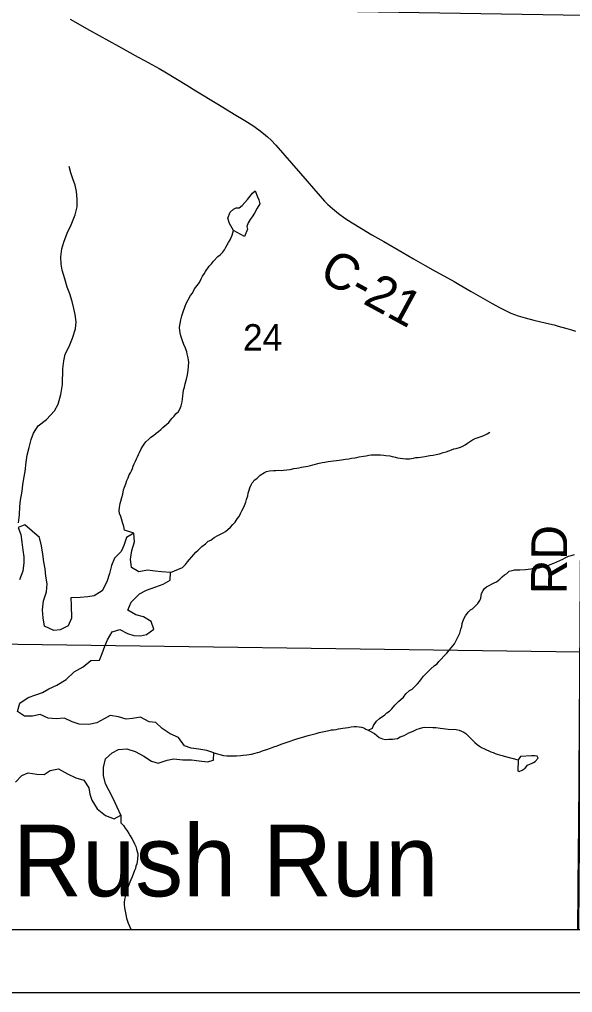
# Model space of a CAD drawing. Extents: x -8.8 to 41.4, y 0 to 34.6.
# Drawn here: x -6.331 to -5.453, y 14 to 15.544 of the extents above; entities that cross this region are included whole.
import ezdxf

# ---------------------------------------------------------------- set-up
doc = ezdxf.new("R2010")
doc.units = 0
for name, color, linetype in [('GM_X_Corporation', 7, 'Continuous'), ('GM_X_County_Road', 7, 'Continuous'), ('GM_X_Minor_River', 7, 'Continuous'), ('GM_X_State_Shield', 7, 'Continuous'), ('GM_X_Township_Road_Text', 7, 'Continuous'), ('GM_X_Township_Text', 7, 'Continuous'), ('GM_X_Unincorporated_Text', 7, 'Continuous'), ('SH_Border', 7, 'Continuous')]:
    doc.layers.add(name, color=color, linetype=linetype)

msp = doc.modelspace()

# ---------------------------------------------------------------- linework, layer by layer
at = {"layer": 'GM_X_Corporation'}
msp.add_lwpolyline([(-8.6743, 18.6925), (-8.6743, 14.1), (-5.4442, 14.1), (-5.4432, 14.2265), (-5.4429, 14.2618), (-5.4404, 14.5882), (-5.4368, 15.0446), (-5.435, 15.3164), (-5.4282, 16.3507), (-5.4212, 16.5483), (-5.4129, 17.3836), (-5.4008, 18.6369)], dxfattribs=at)
for points in [[(-6.4479, 15.5667), (-5.4349, 15.5503), (-5.4351, 15.4586), (-5.4406, 14.5401), (-6.4506, 14.5538)], [(-6.4536, 14.1), (-5.4429, 14.1), (-5.4401, 14.4488), (-5.4406, 14.5401), (-6.4506, 14.5538)]]:
    msp.add_lwpolyline(points, close=True, dxfattribs=at)
at = {"layer": 'GM_X_County_Road'}
msp.add_lwpolyline([(-6.2505, 15.5442), (-6.2195, 15.527), (-6.1739, 15.5016), (-6.1424, 15.4841), (-6.1321, 15.4785), (-6.1092, 15.4658), (-6.0973, 15.4591), (-6.065, 15.4393), (-6.0507, 15.4306), (-6.0151, 15.4089), (-5.9902, 15.3937), (-5.9732, 15.3833), (-5.9606, 15.3753), (-5.9509, 15.3686), (-5.9434, 15.363), (-5.9371, 15.3577), (-5.9313, 15.3521), (-5.924, 15.3444), (-5.9097, 15.328), (-5.8991, 15.3158), (-5.8849, 15.2994), (-5.8743, 15.2872), (-5.8642, 15.2754), (-5.8536, 15.2633), (-5.8464, 15.2556), (-5.8411, 15.2504), (-5.8338, 15.2438), (-5.8242, 15.236), (-5.8141, 15.2287), (-5.8028, 15.2212), (-5.788, 15.2121), (-5.7714, 15.2023), (-5.7618, 15.1967), (-5.7526, 15.1914), (-5.7235, 15.1747), (-5.7052, 15.1641), (-5.687, 15.1535), (-5.6745, 15.1465), (-5.6408, 15.1278), (-5.6327, 15.1232), (-5.6139, 15.1124), (-5.6026, 15.1059), (-5.5805, 15.0932), (-5.5679, 15.0864), (-5.5591, 15.0819), (-5.5507, 15.078), (-5.5391, 15.0737), (-5.5279, 15.0702), (-5.5141, 15.0666), (-5.4942, 15.0619), (-5.4821, 15.059), (-5.4754, 15.0574), (-5.4616, 15.0537), (-5.4544, 15.0515), (-5.4483, 15.0493)], dxfattribs=at)
at = {"layer": 'GM_X_Minor_River'}
for points in [[(-6.3324, 14.7451), (-6.3309, 14.7576), (-6.3301, 14.7709), (-6.3291, 14.7811), (-6.3267, 14.7955), (-6.3253, 14.8053), (-6.3239, 14.8155), (-6.322, 14.8268), (-6.32, 14.8412), (-6.3186, 14.8526), (-6.3155, 14.8646), (-6.3125, 14.8771), (-6.3088, 14.8872), (-6.3012, 14.8988), (-6.288, 14.909), (-6.2751, 14.923), (-6.2695, 14.9335), (-6.2652, 14.9489), (-6.2628, 14.9648), (-6.2621, 14.9895), (-6.2606, 15.0024), (-6.2584, 15.0125), (-6.2519, 15.0249), (-6.2466, 15.038), (-6.242, 15.0527), (-6.2409, 15.0641), (-6.2425, 15.0755), (-6.2444, 15.085), (-6.2471, 15.0961), (-6.251, 15.1084), (-6.2552, 15.1192), (-6.2586, 15.1322), (-6.2631, 15.146), (-6.2647, 15.1555), (-6.2651, 15.1669), (-6.2636, 15.1798), (-6.2606, 15.1903), (-6.2549, 15.2046), (-6.2488, 15.2181), (-6.2426, 15.2339), (-6.2392, 15.2467), (-6.2392, 15.2588), (-6.2404, 15.271), (-6.2424, 15.2806), (-6.2463, 15.2909), (-6.2494, 15.3005), (-6.2521, 15.3105)], [(-5.991, 15.2089), (-5.9976, 15.2201), (-6, 15.2285), (-5.9966, 15.2379), (-5.9908, 15.2427), (-5.9866, 15.2448), (-5.982, 15.2451), (-5.9773, 15.2487), (-5.9687, 15.2583), (-5.9608, 15.2684), (-5.9565, 15.2716), (-5.953, 15.2624), (-5.9509, 15.2574), (-5.9492, 15.2513), (-5.9536, 15.2442), (-5.9576, 15.2364), (-5.9616, 15.2304), (-5.9644, 15.2263), (-5.9679, 15.2211), (-5.97, 15.2155), (-5.969, 15.2109), (-5.9735, 15.1992)], [(-6.0938, 14.9044), (-6.091, 14.9078), (-6.0883, 14.9111), (-6.0851, 14.9145), (-6.0824, 14.9178), (-6.0785, 14.9219), (-6.0761, 14.9256), (-6.074, 14.9305), (-6.0723, 14.9373), (-6.0722, 14.9415), (-6.0717, 14.9464), (-6.0708, 14.9509), (-6.0703, 14.9555), (-6.069, 14.9604), (-6.0677, 14.9657), (-6.0665, 14.9694), (-6.0656, 14.9732), (-6.0639, 14.98), (-6.0634, 14.9834), (-6.0629, 14.9876), (-6.0624, 14.9932), (-6.0622, 15.0001), (-6.0628, 15.0069), (-6.0645, 15.0131), (-6.0652, 15.0165), (-6.0673, 15.0223), (-6.0698, 15.028), (-6.0719, 15.0338), (-6.0743, 15.0403), (-6.0754, 15.0438), (-6.0764, 15.0499), (-6.0766, 15.0556), (-6.0756, 15.0616), (-6.0747, 15.0673), (-6.073, 15.0733), (-6.071, 15.0797), (-6.0677, 15.0888), (-6.066, 15.0929), (-6.0592, 15.1056), (-6.0561, 15.1093), (-6.0528, 15.1165), (-6.0489, 15.1217), (-6.0453, 15.1265), (-6.0425, 15.1321), (-6.0405, 15.1363), (-6.0377, 15.1404), (-6.0354, 15.1441), (-6.0298, 15.1523), (-6.0259, 15.156), (-6.0228, 15.1601), (-6.0157, 15.1675), (-6.0122, 15.1704), (-6.0087, 15.1741), (-6.0052, 15.1782), (-6.0032, 15.1823), (-6.0012, 15.1861), (-5.9988, 15.1898), (-5.9964, 15.1939), (-5.9947, 15.198), (-5.9931, 15.2014), (-5.9919, 15.2052), (-5.991, 15.2089)], [(-5.9735, 15.1992), (-5.991, 15.2089)], [(-6.1492, 14.729), (-6.1639, 14.7335), (-6.1652, 14.7393), (-6.1666, 14.7442), (-6.1701, 14.755), (-6.1718, 14.76), (-6.1728, 14.7649), (-6.1723, 14.7695), (-6.171, 14.7759), (-6.1702, 14.7793), (-6.1685, 14.7853), (-6.1668, 14.7906), (-6.1655, 14.7974), (-6.1642, 14.8019), (-6.1622, 14.8072), (-6.1605, 14.8121), (-6.1585, 14.8166), (-6.1568, 14.8211), (-6.1548, 14.8245), (-6.1532, 14.8278), (-6.1516, 14.8316), (-6.1504, 14.835), (-6.1487, 14.8387), (-6.1467, 14.8429), (-6.1451, 14.8466), (-6.1435, 14.85), (-6.1419, 14.8534), (-6.1403, 14.8567), (-6.1374, 14.8624), (-6.135, 14.8669), (-6.1331, 14.8702), (-6.1303, 14.8736), (-6.1256, 14.878), (-6.1221, 14.8809), (-6.1179, 14.8838), (-6.114, 14.8872), (-6.1101, 14.8901), (-6.1066, 14.8934), (-6.1031, 14.8964), (-6.0938, 14.9044)], [(-5.7575, 14.8528), (-5.7526, 14.8523), (-5.7492, 14.8518), (-5.7428, 14.8512), (-5.739, 14.8504), (-5.7341, 14.8491), (-5.7307, 14.8482), (-5.7224, 14.8472), (-5.7175, 14.8467), (-5.7118, 14.8469), (-5.7053, 14.8475), (-5.7015, 14.8486), (-5.6981, 14.8488), (-5.6943, 14.8495), (-5.6905, 14.8498), (-5.6844, 14.8507), (-5.6794, 14.8517), (-5.6741, 14.8527), (-5.6691, 14.8537), (-5.6638, 14.8547), (-5.6584, 14.8568), (-5.6534, 14.8578), (-5.6492, 14.8596), (-5.645, 14.861), (-5.6411, 14.8628), (-5.6373, 14.8631), (-5.6324, 14.8648), (-5.6282, 14.8662), (-5.6231, 14.8691), (-5.6197, 14.8713), (-5.6162, 14.8739), (-5.6115, 14.8768), (-5.6073, 14.879), (-5.5996, 14.8818), (-5.5962, 14.8828), (-5.5927, 14.8842), (-5.5881, 14.8864), (-5.5843, 14.8889)], [(-6.0911, 14.6665), (-6.0722, 14.6743), (-6.0675, 14.6791), (-6.064, 14.6832), (-6.0609, 14.6869), (-6.0573, 14.691), (-6.0538, 14.6951), (-6.0507, 14.6984), (-6.0472, 14.7017), (-6.0413, 14.7077), (-6.0355, 14.7117), (-6.0312, 14.7161), (-6.027, 14.7179), (-6.0219, 14.7219), (-6.0158, 14.7248), (-6.0108, 14.7277), (-6.0073, 14.7291), (-6.0038, 14.7313), (-6.0003, 14.7346), (-5.9957, 14.7383), (-5.9921, 14.7424), (-5.9882, 14.7464), (-5.985, 14.7513), (-5.9823, 14.7554), (-5.9799, 14.7599), (-5.9778, 14.764), (-5.9754, 14.7689), (-5.9738, 14.7726), (-5.9714, 14.7779), (-5.9705, 14.782), (-5.9684, 14.7881), (-5.9676, 14.7922), (-5.9663, 14.7971), (-5.965, 14.8009), (-5.963, 14.8054), (-5.9614, 14.8088), (-5.9571, 14.8132), (-5.9536, 14.8158), (-5.9489, 14.8206), (-5.942, 14.8249), (-5.9385, 14.8267), (-5.9339, 14.8277), (-5.9278, 14.8283), (-5.924, 14.8282), (-5.9199, 14.8285), (-5.9153, 14.8284), (-5.9119, 14.8286), (-5.9062, 14.8292), (-5.9009, 14.8299), (-5.8955, 14.8312), (-5.8906, 14.8318), (-5.8871, 14.8325), (-5.8833, 14.8332), (-5.873, 14.8351), (-5.8688, 14.8362), (-5.865, 14.8372), (-5.8608, 14.8382), (-5.857, 14.8393), (-5.8505, 14.841), (-5.8459, 14.8416), (-5.8405, 14.8426), (-5.8367, 14.8432), (-5.8322, 14.8435), (-5.8276, 14.8441), (-5.8234, 14.8448), (-5.8196, 14.845), (-5.8135, 14.846), (-5.8082, 14.8466), (-5.8036, 14.8476), (-5.7986, 14.8483), (-5.7952, 14.8489), (-5.7914, 14.8496), (-5.7849, 14.8509), (-5.7803, 14.8515), (-5.7761, 14.8526), (-5.7723, 14.8528), (-5.7682, 14.8531), (-5.7621, 14.8529), (-5.7575, 14.8528)], [(-5.7771, 14.4163), (-5.7706, 14.4196), (-5.7686, 14.4237), (-5.7638, 14.4304), (-5.7592, 14.4345), (-5.7507, 14.4403), (-5.7475, 14.4436), (-5.7436, 14.4466), (-5.7398, 14.4499), (-5.7347, 14.4558), (-5.7292, 14.4617), (-5.7214, 14.4687), (-5.7175, 14.4736), (-5.7116, 14.4791), (-5.7074, 14.4813), (-5.7031, 14.4853), (-5.6988, 14.4898), (-5.6952, 14.4942), (-5.6925, 14.4976), (-5.6893, 14.5017), (-5.6846, 14.5068), (-5.6784, 14.5131), (-5.6718, 14.519), (-5.6679, 14.5216), (-5.6652, 14.5249), (-5.6616, 14.529), (-5.6569, 14.5334), (-5.6523, 14.5382), (-5.6479, 14.5434), (-5.6401, 14.5531), (-5.6373, 14.5583), (-5.6348, 14.5636), (-5.6316, 14.5703), (-5.6303, 14.5767), (-5.6287, 14.5809), (-5.6278, 14.5854), (-5.6269, 14.5888), (-5.6249, 14.5941), (-5.6229, 14.5978), (-5.6185, 14.6034), (-5.615, 14.6071), (-5.6116, 14.6089), (-5.6077, 14.6126), (-5.603, 14.6174), (-5.6002, 14.6219), (-5.5986, 14.6256), (-5.5977, 14.6294), (-5.5972, 14.6328), (-5.5948, 14.6377), (-5.5928, 14.6411), (-5.5893, 14.6436), (-5.5851, 14.6458), (-5.5816, 14.6476), (-5.5774, 14.6497), (-5.5735, 14.6515), (-5.5681, 14.6556), (-5.5646, 14.6593), (-5.5607, 14.6626), (-5.5572, 14.6647), (-5.5533, 14.6684), (-5.5484, 14.6694), (-5.5449, 14.6705), (-5.5407, 14.6707), (-5.5366, 14.6706), (-5.5275, 14.6711), (-5.5233, 14.6718), (-5.5187, 14.6724), (-5.5145, 14.673), (-5.5099, 14.6733), (-5.5058, 14.6736), (-5.5023, 14.6746), (-5.497, 14.6756), (-5.4924, 14.677), (-5.4882, 14.6788), (-5.4824, 14.6809), (-5.4732, 14.6852), (-5.4682, 14.6877), (-5.4643, 14.6895), (-5.4593, 14.692), (-5.4547, 14.6934), (-5.4498, 14.6948)], [(-5.9155, 14.394), (-5.9105, 14.3958), (-5.9044, 14.3979), (-5.9009, 14.3989), (-5.8952, 14.4011), (-5.8887, 14.4028), (-5.8833, 14.4045), (-5.8776, 14.4063), (-5.8726, 14.408), (-5.8642, 14.4101), (-5.8596, 14.4111), (-5.855, 14.4125), (-5.8497, 14.4135), (-5.8447, 14.4145), (-5.8394, 14.4158), (-5.8356, 14.4165), (-5.8321, 14.4168), (-5.8279, 14.4174), (-5.8245, 14.4181), (-5.8207, 14.4187), (-5.8173, 14.4194), (-5.8089, 14.4207), (-5.8043, 14.4213), (-5.7994, 14.4219), (-5.7956, 14.4218), (-5.7914, 14.4213), (-5.7876, 14.4208), (-5.7842, 14.42), (-5.7809, 14.418), (-5.7771, 14.4163), (-5.7674, 14.4108), (-5.7633, 14.408), (-5.76, 14.4045), (-5.7544, 14.4024), (-5.7495, 14.4015), (-5.7442, 14.4017), (-5.7385, 14.402), (-5.7347, 14.4022), (-5.7305, 14.4032), (-5.7262, 14.4054), (-5.7201, 14.4079), (-5.7166, 14.4101), (-5.7128, 14.4119), (-5.7085, 14.4137), (-5.7047, 14.4154), (-5.6997, 14.4176), (-5.6959, 14.419), (-5.6905, 14.4204), (-5.6871, 14.421), (-5.6746, 14.4207), (-5.6696, 14.4202), (-5.6662, 14.4201), (-5.6628, 14.4196), (-5.6583, 14.4187), (-5.6545, 14.4182), (-5.65, 14.4177), (-5.6375, 14.4173), (-5.6326, 14.4164), (-5.6292, 14.4145), (-5.6255, 14.4128), (-5.6221, 14.4108), (-5.6188, 14.4077), (-5.6155, 14.4042), (-5.6114, 14.4003), (-5.6081, 14.3968), (-5.6044, 14.3936), (-5.6007, 14.3908), (-5.5973, 14.3889), (-5.5928, 14.3868), (-5.5827, 14.382), (-5.5789, 14.3807), (-5.5756, 14.3791), (-5.5722, 14.3779), (-5.5688, 14.377), (-5.5647, 14.3758), (-5.5613, 14.3749)], [(-6.0223, 14.3804), (-6.0067, 14.3761), (-6.0014, 14.3755), (-5.9915, 14.3753), (-5.9862, 14.3755), (-5.9794, 14.3761), (-5.9759, 14.3767), (-5.9699, 14.3769), (-5.9626, 14.3783), (-5.9569, 14.3796), (-5.9531, 14.381), (-5.9488, 14.382), (-5.9439, 14.3838), (-5.9381, 14.3855), (-5.9324, 14.3877), (-5.927, 14.3898), (-5.9216, 14.3915), (-5.9155, 14.394)], [(-5.5613, 14.3749), (-5.5392, 14.369)], [(-5.5392, 14.369), (-5.5397, 14.3519), (-5.5375, 14.3507), (-5.5325, 14.3528), (-5.5282, 14.3557), (-5.5243, 14.3605), (-5.517, 14.3637), (-5.5147, 14.3648), (-5.512, 14.3663), (-5.5076, 14.3718), (-5.5091, 14.3749), (-5.5128, 14.3754), (-5.5178, 14.3755)], [(-5.5178, 14.3755), (-5.5356, 14.3746), (-5.5392, 14.369)], [(-6.1702, 14.2815), (-6.1698, 14.2693), (-6.1658, 14.2647), (-6.1629, 14.2608), (-6.16, 14.2565), (-6.157, 14.2523), (-6.1549, 14.2484), (-6.1523, 14.2445), (-6.1505, 14.2407), (-6.148, 14.236), (-6.1462, 14.2318), (-6.1448, 14.2276), (-6.1438, 14.2238), (-6.1432, 14.2199), (-6.1434, 14.2112), (-6.1439, 14.2078), (-6.1447, 14.2044), (-6.146, 14.2003), (-6.1469, 14.1969), (-6.1485, 14.1935), (-6.1522, 14.1833), (-6.1542, 14.1788), (-6.1558, 14.1751), (-6.1571, 14.1709), (-6.1591, 14.1653), (-6.1608, 14.1612), (-6.1624, 14.1574), (-6.1633, 14.1517), (-6.1642, 14.1476), (-6.1647, 14.143), (-6.1644, 14.1396), (-6.1642, 14.1346), (-6.1632, 14.1293), (-6.1622, 14.1236), (-6.1609, 14.1178), (-6.1584, 14.1098), (-6.1541, 14.1005), (-6.1535, 14.1)]]:
    msp.add_lwpolyline(points, dxfattribs=at)
at = {"layer": 'GM_X_State_Shield'}
for points in [[(-6.2038, 14.5271), (-6.1994, 14.5376), (-6.1956, 14.5496), (-6.1911, 14.5597), (-6.1835, 14.5721), (-6.1716, 14.5759), (-6.1593, 14.5694), (-6.1492, 14.5665), (-6.1389, 14.5658), (-6.1294, 14.5678), (-6.1177, 14.5765), (-6.1219, 14.5888), (-6.1339, 14.596), (-6.1459, 14.5994), (-6.1586, 14.6066), (-6.1533, 14.6194), (-6.1404, 14.6323), (-6.1292, 14.6384), (-6.1146, 14.6437), (-6.1027, 14.6479), (-6.0915, 14.654), (-6.0911, 14.6665), (-6.1052, 14.6673), (-6.1154, 14.6684), (-6.1278, 14.6703), (-6.1416, 14.6673), (-6.1531, 14.6744), (-6.1547, 14.6874), (-6.1527, 14.7014), (-6.1485, 14.7149), (-6.1492, 14.729), (-6.1612, 14.7218), (-6.1654, 14.7094), (-6.1695, 14.6996), (-6.18, 14.6889), (-6.1845, 14.6777), (-6.188, 14.6645), (-6.1922, 14.6513), (-6.1994, 14.6375), (-6.2125, 14.6295), (-6.2221, 14.6275), (-6.2346, 14.6267), (-6.2491, 14.6264), (-6.249, 14.6143), (-6.2481, 14.5937), (-6.2538, 14.5817), (-6.2665, 14.5753), (-6.2764, 14.5741), (-6.291, 14.5813), (-6.2933, 14.5943), (-6.2944, 14.6073), (-6.2925, 14.6216), (-6.2879, 14.6356), (-6.2867, 14.6484), (-6.289, 14.6607), (-6.2902, 14.6721), (-6.2921, 14.6835), (-6.2937, 14.6954), (-6.2959, 14.7087), (-6.2993, 14.7217), (-6.3223, 14.7422), (-6.333, 14.7379), (-6.3288, 14.7264), (-6.3273, 14.7146), (-6.3257, 14.702), (-6.3242, 14.6913), (-6.3237, 14.6818), (-6.3256, 14.6686), (-6.3309, 14.6547)], [(-6.2296, 14.5168), (-6.2175, 14.5267), (-6.2038, 14.5271)], [(-6.3371, 14.3336), (-6.3269, 14.3443), (-6.3173, 14.3486), (-6.3034, 14.3466), (-6.2916, 14.3459), (-6.2819, 14.3521), (-6.2689, 14.3551), (-6.2548, 14.3471), (-6.2413, 14.3406), (-6.2289, 14.3368), (-6.2205, 14.3248), (-6.2193, 14.3149), (-6.2162, 14.3049), (-6.2075, 14.2913), (-6.1945, 14.2807), (-6.1803, 14.2753), (-6.1702, 14.2815), (-6.1755, 14.2942), (-6.182, 14.3077), (-6.1891, 14.3208), (-6.1945, 14.3308), (-6.1972, 14.3442), (-6.1976, 14.3568), (-6.1941, 14.3707), (-6.1836, 14.3803), (-6.1735, 14.3857), (-6.1606, 14.3868), (-6.1471, 14.3822), (-6.1336, 14.375), (-6.121, 14.367), (-6.1108, 14.3637), (-6.0966, 14.3685), (-6.086, 14.3705), (-6.0716, 14.3689), (-6.0579, 14.3689), (-6.0458, 14.3678), (-6.0326, 14.3659), (-6.023, 14.3686), (-6.0223, 14.3804), (-6.0336, 14.3841), (-6.046, 14.386), (-6.0581, 14.3875), (-6.069, 14.3913), (-6.0785, 14.4045), (-6.0916, 14.4102), (-6.1043, 14.4189), (-6.1146, 14.4283), (-6.1252, 14.4294), (-6.1386, 14.4366), (-6.1516, 14.4348), (-6.1615, 14.4339), (-6.1735, 14.4373), (-6.1867, 14.4396), (-6.1964, 14.4342), (-6.2079, 14.4281), (-6.2209, 14.4251), (-6.2361, 14.4255), (-6.2474, 14.4296), (-6.2593, 14.4353), (-6.2726, 14.4342), (-6.2851, 14.4353), (-6.2979, 14.441), (-6.3101, 14.4384), (-6.323, 14.4384), (-6.3338, 14.4459), (-6.3303, 14.4591), (-6.3172, 14.4678), (-6.3049, 14.472), (-6.2945, 14.4762), (-6.2841, 14.4816), (-6.2718, 14.4877), (-6.2567, 14.4968), (-6.2439, 14.5085), (-6.2296, 14.5168)]]:
    msp.add_lwpolyline(points, dxfattribs=at)
at = {"layer": 'SH_Border'}
for p, q in [((-8.6743, 14.1), (-1.8743, 14.1)), ((-8.7743, 14), (-1.7743, 14))]:
    msp.add_line(p, q, dxfattribs=at)

# ---------------------------------------------------------------- texts
at = {"layer": 'GM_X_Township_Road_Text'}
for s, rotation, p in [('C-21', 331.4441, (-5.8577, 15.1322)), ('RD', 89.5063, (-5.462, 14.6316))]:
    msp.add_text(s, height=0.05682, rotation=rotation, dxfattribs=at).set_placement(p)
at = {"layer": 'GM_X_Township_Text'}
msp.add_text('24', height=0.04186, rotation=0, dxfattribs=at).set_placement((-5.9759, 15.0185))
at = {"layer": 'GM_X_Unincorporated_Text'}
msp.add_text('Rush Run', height=0.11363, rotation=359.9986, dxfattribs=at).set_placement((-6.3413, 14.1526))

doc.saveas('drawing.dxf')
